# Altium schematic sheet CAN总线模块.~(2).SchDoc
size A4
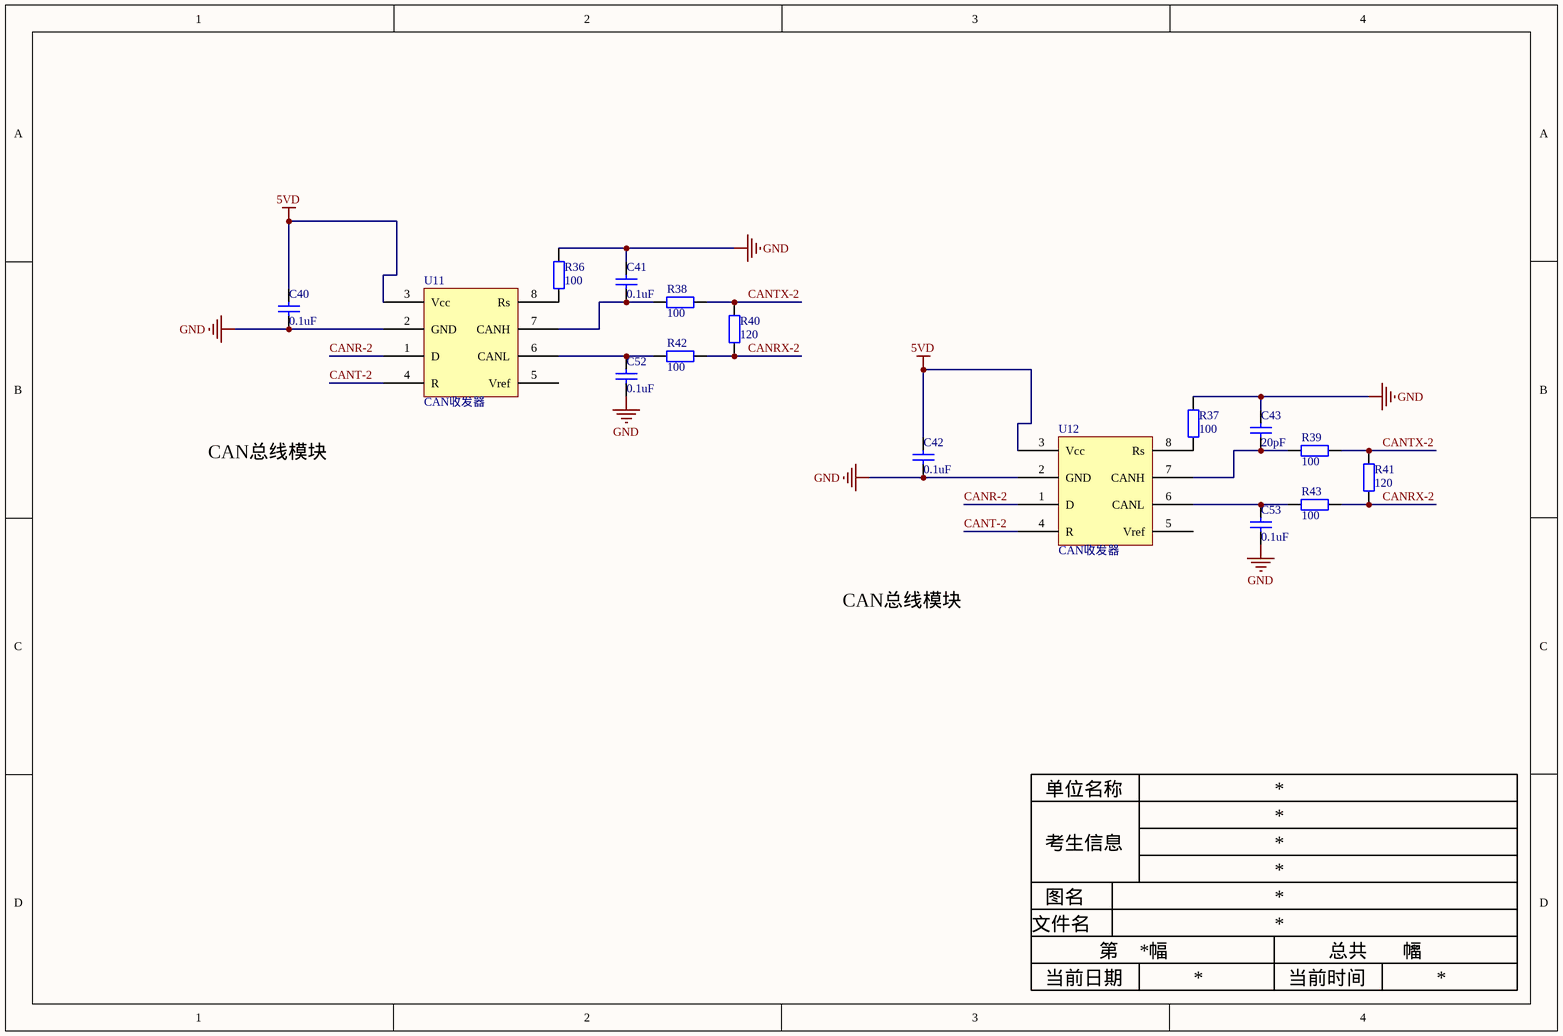
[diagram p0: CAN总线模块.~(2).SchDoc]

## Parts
C40  value 0.1uF  [RAD-0.3]  (hidden comment: Cap)
C41  value 0.1uF  [RAD-0.3]  (hidden comment: Cap)
C42  value 0.1uF  [RAD-0.3]  (hidden comment: Cap)
C43  value 20pF  [RAD-0.3]  (hidden comment: Cap)
C52  value 0.1uF  [RAD-0.3]  (hidden comment: Cap)
C53  value 0.1uF  [RAD-0.3]  (hidden comment: Cap)
R36  100  [R0603]
R37  100  [R0603]
R38  100  [R0603]
R39  100  [R0603]
R40  120  [R0603]
R41  120  [R0603]
R42  100  [R0603]
R43  100  [R0603]
U11  CAN收发器  [CAN]
U12  CAN收发器  [CAN]

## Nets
5VD: C40.2 C42.2 U11.3(Vcc) U12.3(Vcc)
GND: C40.1 C41.2 C42.1 C43.2 C52.1 C53.1 R36.2 R37.2 U11.2(GND) U12.2(GND)
CANR-2: U11.1(D) U12.1(D)
CANRX-2: R40.2 R41.2 R42.1 R43.1
CANT-2: U11.4(R) U12.4(R)
CANTX-2: R38.1 R39.1 R40.1 R41.1
NetC41_1: C41.1 R38.2 U11.7(CANH)
NetC43_1: C43.1 R39.2 U12.7(CANH)
NetC52_2: C52.2 R42.2 U11.6(CANL)
NetC53_2: C53.2 R43.2 U12.6(CANL)
NetR36_1: R36.1 U11.8(Rs)
NetR37_1: R37.1 U12.8(Rs)

Not connected (* = marked no-connect by the designer): U11 5(Vref); U12 5(Vref)

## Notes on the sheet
- 单位名称
- 考生信息
- 图名
- 文件名
- 当前日期
- 第      幅
- 当前时间
- 总共       幅
- Labels drawn without touching a wire or pin: CAN总线模块

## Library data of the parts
C40-C43 C52 C53 = Cap: Capacitor
R36-R43 = R0603
U11 U12 = CAN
